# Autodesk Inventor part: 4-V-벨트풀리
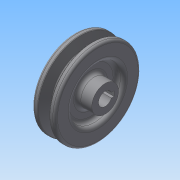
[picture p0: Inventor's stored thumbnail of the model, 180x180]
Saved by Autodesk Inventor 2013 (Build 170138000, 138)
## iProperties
Created: 2015-02
Part Number: 4-V-벨트풀리
Material: 일반
Document SubType Name: Modeling
Designer: Administrator
Density: 1 g/cm^3
Author: Administrator
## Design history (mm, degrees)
sketch "스케치1"
  geometry: L1 (0, 0)-(25, 0); L2 (0, 0)-(0, 11); L3 (0, 11)-(6, 11); L4 (6, 11)-(6, 21.5); L5 (6, 21.5)-(0, 21.5); L6 (0, 21.5)-(0, 35.2); L7 (0, 35.2)-(4.675, 35.2); L8 (4.675, 35.2)-(7.426, 26.2); L9 (7.426, 26.2)-(11.574, 26.2); L10 (11.574, 26.2)-(14.325, 35.2); L11 (14.325, 35.2)-(19, 35.2); L12 (19, 35.2)-(19, 21.5); L13 (19, 21.5)-(13, 21.5); L14 (13, 21.5)-(13, 11); L15 (13, 11)-(25, 11); L16 (25, 11)-(25, 0); 2 further points
  constraints: 32 end point, 9 parallel, 5 collinear, 3 equal length, 3 point on line, 2 perpendicular, 1 horizontal, 1 horizontal alignment
  dimensions: "d0" = 25 distance of L1.start L1.end; "d1" = 22 diameter of L15 L1; "d2" = 43 diameter of L5 L1; "d3" = 2.7 distance from line of point (13.5, 32.5) L11; "d4" = 6.3 distance from line of L9 point (13.5, 32.5); "d5" = 8 distance of point (13.5, 32.5) point (5.5, 32.5); "d6" = 34 deg angle of L10 L8; "d7" = 65 diameter of point (5.5, 32.5) L1; "d8" = 19 distance between parallel lines of L12 L6; "d9" = 6 distance of L4.end L5.end
revolve "회전1" sketch "스케치1" stored, may be unused: angle "d10" = 90 deg
sketch "스케치2"
  geometry: L1 (-2, 5.123)-(-2, 7.3); L2 (-2, 7.3)-(2, 7.3); L3 (2, 7.3)-(2, 5.123); C1 r 11 at (0, 0) reference; A1 r 5.5 centre (0, 0) between (-2, 5.123) and (2, 5.123); 1 further point
  constraints: 6 end point, 2 point on circle, 1 centre point, 1 coincident, 1 midpoint, 1 parallel, 1 perpendicular, 1 vertical, 1 vertical alignment
  dimensions: "d11" = 11 diameter of A1; "d13" = 4 distance of L1.end L2.end; "d14" = 12.8 dimension on A1 L2
extrude "돌출1" cut sketch "스케치2" stored distance "d15" = 10; taper "d16" = 0 deg
fillet "모깎기1" dims "d17" = 1, "d18" = 0.5, "d19" = 2
fillet "모깎기2" dims "d20" = 3
node "솔리드1"
